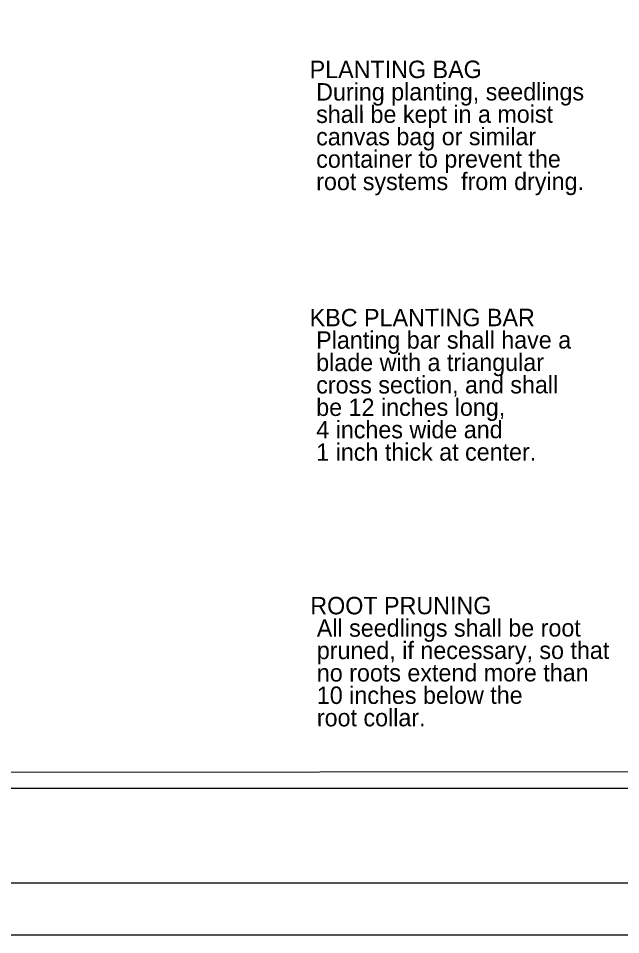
# Model space of a CAD drawing. Extents: x 816132 to 817815, y 885694 to 886789.
# Drawn here: x 816576.6 to 816808.5, y 885693.9 to 886046.5 of the extents above; entities that cross this region are included whole.
import ezdxf

# ---------------------------------------------------------------- set-up
doc = ezdxf.new("R2010")
doc.units = 0
for name, color, linetype in [('Sheet Plot Border Inside CELL', 7, 'Continuous'), ('Sheet Plot Border Outside CELL', 7, 'Continuous'), ('Silt Fence Coir Fiber Wattle Break Detail CELL', 7, 'Continuous')]:
    doc.layers.add(name, color=color, linetype=linetype)

msp = doc.modelspace()

# ---------------------------------------------------------------- linework, layer by layer
at = {"layer": 'Sheet Plot Border Inside CELL'}
msp.add_lwpolyline([(816131.57, 885693.89), (817815.07, 885693.89), (817815.07, 886788.89), (816131.57, 886788.89)], close=True, dxfattribs=at)
at = {"layer": 'Sheet Plot Border Outside CELL'}
msp.add_lwpolyline([(816144.57, 885713.89), (817810.57, 885713.89), (817810.57, 886768.89), (816144.57, 886768.89)], close=True, dxfattribs=at)
at = {"layer": 'Silt Fence Coir Fiber Wattle Break Detail CELL'}
msp.add_line((816277.92, 885756.19), (817017.37, 885756.77), dxfattribs=at)
msp.add_lwpolyline([(817809.42, 886749.78), (816263.39, 886749.78), (816263.39, 885750.31), (817809.42, 885750.31)], close=True, dxfattribs=at)

# ---------------------------------------------------------------- texts
for s, p in [('PLANTING BAG ', (816688.77, 886023.43)), (' During planting, seedlings', (816688.78, 886014.81)), (' shall be kept in a moist ', (816688.79, 886006.19)), (' canvas bag or similar', (816688.79, 885997.57)), (' container to prevent the ', (816688.8, 885988.95)), (' root systems  from drying.', (816688.8, 885980.33)), ('KBC PLANTING BAR', (816688.79, 885927.94)), (' Planting bar shall have a', (816688.79, 885919.32)), (' blade with a triangular', (816688.8, 885910.7)), (' cross section, and shall', (816688.81, 885902.08)), (' be 12 inches long,', (816688.81, 885893.46)), (' 4 inches wide and ', (816688.82, 885884.84)), (' 1 inch thick at center.', (816688.82, 885876.22)), ('ROOT PRUNING ', (816689.03, 885817.13)), (' All seedlings shall be root', (816689.03, 885808.51)), (' pruned, if necessary, so that', (816689.04, 885799.89)), (' no roots extend more than ', (816689.04, 885791.27)), (' 10 inches below the', (816689.05, 885782.65)), (' root collar.', (816689.06, 885774.03))]:
    msp.add_text(s, height=6.7041, rotation=0.045, dxfattribs=at).set_placement(p)

doc.saveas('drawing.dxf')
